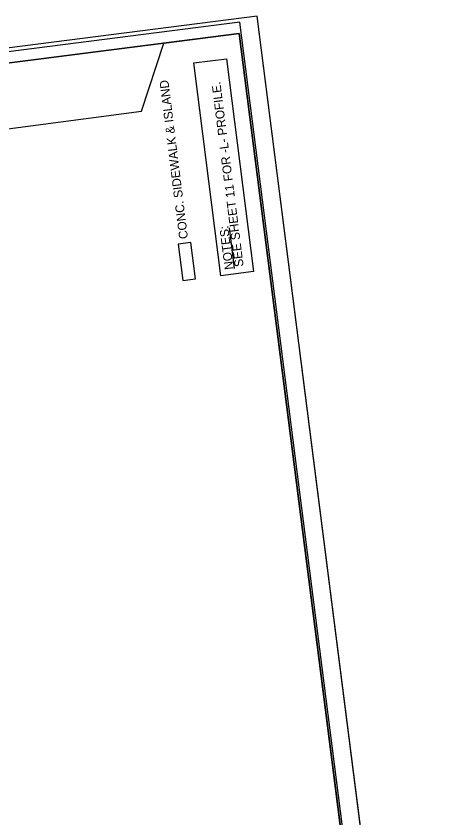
# Model space of a CAD drawing. Extents: x 2368054 to 2369353, y 804567 to 806376.
# Drawn here: x 2368868 to 2369353, y 805472 to 806376 of the extents above; entities that cross this region are included whole.
import ezdxf

# ---------------------------------------------------------------- set-up
doc = ezdxf.new("R2010")
doc.units = 0
for name, color, linetype in [('Old_Level_10', 7, 'Continuous'), ('Old_Level_15', 7, 'Continuous'), ('Old_Level_2', 7, 'Continuous'), ('Old_Level_4', 7, 'Continuous'), ('Old_Level_5', 7, 'Continuous'), ('Old_Level_6', 7, 'Continuous'), ('Old_Level_9', 7, 'Continuous'), ('Plot Label CELL', 7, 'Continuous'), ('Plot Shape CELL', 7, 'Continuous')]:
    doc.layers.add(name, color=color, linetype=linetype)

msp = doc.modelspace()

# ---------------------------------------------------------------- linework, layer by layer
at = {"layer": 'Old_Level_10'}
msp.add_lwpolyline([(2368268.35, 804735.15), (2369309.86, 804868.2), (2369119.83, 806356.11), (2368288.07, 806249.88), (2368318.38, 806012.56), (2368108.6, 805985.76)], close=True, dxfattribs=at)
at = {"layer": 'Old_Level_15'}
msp.add_line((2369353.29, 804705.9), (2369140, 806375.84), dxfattribs=at)
at = {"layer": 'Old_Level_2'}
msp.add_lwpolyline([(2369128.07, 804972.39), (2369136.27, 804907.55), (2368256.12, 804830.92), (2368108.6, 805985.76), (2368318.38, 806012.56), (2368297.7, 806174.49), (2369009.69, 806268.56), (2369034.65, 806345.24), (2369119.83, 806356.12), (2369293.89, 804993.26)], close=True, dxfattribs=at)
msp.add_lwpolyline([(2369128.07, 804972.39), (2369136.27, 804907.55), (2368256.12, 804830.92), (2368108.6, 805985.76), (2368318.38, 806012.56), (2368297.7, 806174.49), (2369009.69, 806268.56), (2369034.65, 806345.24), (2369119.83, 806356.12), (2369293.89, 804993.26)], close=True, dxfattribs=at)
at = {"layer": 'Old_Level_4'}
msp.add_lwpolyline([(2369331.8, 804716.26), (2369120.73, 806368.83), (2368074.24, 806235.18), (2368285.3, 804582.61)], close=True, dxfattribs=at)
at = {"layer": 'Old_Level_5'}
msp.add_lwpolyline([(2369070.41, 806079.34), (2369065.29, 806120.34), (2369051.13, 806118.58), (2369056.24, 806077.57), (2369070.41, 806079.34)], dxfattribs=at)
at = {"layer": 'Old_Level_6'}
msp.add_lwpolyline([(2369353.29, 804705.9), (2369140, 806375.84), (2368053.83, 806237.11), (2368267.11, 804567.18)], close=True, dxfattribs=at)
at = {"layer": 'Old_Level_9'}
msp.add_lwpolyline([(2369070.41, 806079.34), (2369065.29, 806120.34), (2369051.13, 806118.58), (2369056.24, 806077.57), (2369070.41, 806079.34)], dxfattribs=at)
at = {"layer": 'Plot Label CELL'}
msp.add_line((2369114.71, 806091.05), (2369108.86, 806137.17), dxfattribs=at)
msp.add_lwpolyline([(2369099.17, 806082.87), (2369068.51, 806322.94), (2369105.48, 806327.66), (2369136.14, 806087.59)], close=True, dxfattribs=at)
at = {"layer": 'Plot Shape CELL'}
for points in [[(2368078.28, 806223.12), (2368268.32, 804735.17), (2369309.86, 804868.2), (2369119.83, 806356.12)], [(2369309.86, 804868.2), (2368268.35, 804735.15), (2368103.62, 806024.66), (2368252.47, 806043.68), (2368227.14, 806242.11), (2369119.83, 806356.12)]]:
    msp.add_lwpolyline(points, close=True, dxfattribs=at)

# ---------------------------------------------------------------- texts
at = {"layer": 'Plot Label CELL'}
for s, rotation, p in [('CONC. SIDEWALK & ISLAND', 97.10772, (2369062.16, 806125.04)), ('SEE SHEET 11 FOR -L- PROFILE.', 97.22897, (2369124.95, 806093.62)), ('NOTES:', 97.22897, (2369113.59, 806090.44))]:
    msp.add_text(s, height=10, rotation=rotation, dxfattribs=at).set_placement(p)

doc.saveas('drawing.dxf')
